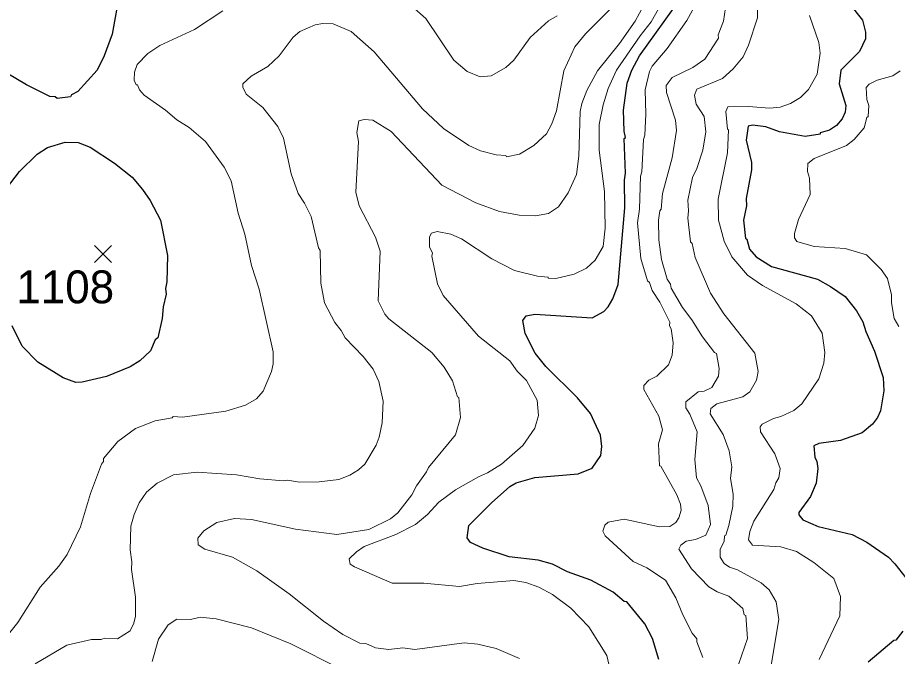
# Model space of a CAD drawing. Extents: x 265.7 to 292.1, y 7676.2 to 7704.2.
# Drawn here: x 288.593 to 290.734, y 7698.298 to 7699.854 of the extents above; entities that cross this region are included whole.
import ezdxf
from ezdxf.enums import TextEntityAlignment as Align

# ---------------------------------------------------------------- set-up
doc = ezdxf.new("R2010")
doc.units = 0
doc.header["$LTSCALE"] = 0.032
for name, color, linetype, lineweight in [('1', 7, 'Continuous', 25), ('2', 7, 'Continuous', 13), ('21', 7, 'Continuous', 25)]:
    doc.layers.add(name, color=color, linetype=linetype, lineweight=lineweight)
doc.layers.add('61', color=7, linetype='Continuous')

msp = doc.modelspace()

# ---------------------------------------------------------------- linework, layer by layer
at = {"layer": '1'}
for points in [[(288.8382, 7699.9938), (288.843, 7699.9587), (288.8398, 7699.9045), (288.823, 7699.8135), (288.8039, 7699.7608), (288.7871, 7699.7257), (288.7393, 7699.6738)], [(289.8221, 7699.1161), (289.8309, 7699.1272), (289.8516, 7699.132), (289.9913, 7699.1225), (290.0192, 7699.1384), (290.0304, 7699.1496), (290.0415, 7699.1688), (290.0543, 7699.2039), (290.0703, 7699.3906), (290.0695, 7699.4576), (290.0726, 7699.4752), (290.0687, 7699.559), (290.0719, 7699.5614), (290.0687, 7699.5773), (290.0671, 7699.6284), (290.0766, 7699.6938), (290.0878, 7699.7257), (290.1062, 7699.7608), (290.2075, 7699.9029)], [(290.6169, 7699.8869), (290.6488, 7699.8478), (290.656, 7699.8183), (290.656, 7699.8023), (290.6416, 7699.7712), (290.5961, 7699.7257), (290.5921, 7699.6922), (290.6081, 7699.6396), (290.6065, 7699.6236), (290.5993, 7699.6076), (290.5858, 7699.5909), (290.5682, 7699.5797), (290.5459, 7699.5733), (290.5459, 7699.5701), (290.5091, 7699.5645), (290.4469, 7699.5757), (290.4134, 7699.5877), (290.3815, 7699.5917), (290.3703, 7699.5893), (290.3655, 7699.555), (290.3791, 7699.5007), (290.3791, 7699.4832), (290.3655, 7699.4129), (290.3663, 7699.3954), (290.3591, 7699.3603), (290.3639, 7699.3156), (290.3671, 7699.314), (290.3743, 7699.29), (290.3902, 7699.2709), (290.4278, 7699.2477), (290.5395, 7699.2166), (290.5714, 7699.1991), (290.6065, 7699.1743), (290.6344, 7699.14), (290.6496, 7699.1129), (290.6568, 7699.089), (290.6783, 7699.0411), (290.6991, 7698.9772), (290.7006, 7698.9453), (290.6927, 7698.8959), (290.6855, 7698.8799), (290.6735, 7698.8639), (290.648, 7698.8424), (290.5953, 7698.824), (290.5427, 7698.8168), (290.5307, 7698.8113), (290.5331, 7698.7833), (290.5379, 7698.773), (290.5403, 7698.7554), (290.5363, 7698.7203), (290.5227, 7698.6876), (290.494, 7698.6485), (290.494, 7698.6429), (290.5036, 7698.6309), (290.5411, 7698.6142), (290.6241, 7698.595), (290.6592, 7698.5766), (290.7118, 7698.5399), (290.7278, 7698.524), (290.7629, 7698.4785)], [(288.7393, 7699.6738), (288.7241, 7699.6659), (288.7217, 7699.6611), (288.6898, 7699.6571), (288.6842, 7699.6611), (288.6714, 7699.6619), (288.6148, 7699.6898), (288.4962, 7699.76)], [(288.5533, 7699.4209), (288.598, 7699.4792), (288.6411, 7699.5214), (288.6658, 7699.5374), (288.7089, 7699.5502), (288.7409, 7699.5494), (288.7696, 7699.5382), (288.8286, 7699.4991), (288.8717, 7699.4648), (288.8972, 7699.4353), (288.9156, 7699.4081), (288.9411, 7699.3603), (288.9579, 7699.2741), (288.9563, 7699.2102), (288.9531, 7699.1943), (288.9547, 7699.1799), (288.9475, 7699.1496), (288.9451, 7699.1209), (288.934, 7699.0738), (288.9276, 7699.069), (288.9164, 7699.0427), (288.8909, 7699.0179), (288.8669, 7699.0036), (288.8095, 7698.9796), (288.7504, 7698.9661), (288.7345, 7698.9653), (288.7042, 7698.9764), (288.6427, 7699.0147), (288.6044, 7699.0538), (288.5797, 7699.1033)], [(290.0112, 7698.8368), (289.9873, 7698.8895), (289.9553, 7698.9278), (289.878, 7699.0044), (289.8524, 7699.0363), (289.8285, 7699.0842), (289.8221, 7699.1161)], [(290.1532, 7698.291), (290.1381, 7698.3421), (290.1189, 7698.3772), (290.0751, 7698.4314), (290.0687, 7698.4322), (290.0423, 7698.4546), (289.9881, 7698.4841), (289.9314, 7698.504), (289.8947, 7698.5232), (289.8596, 7698.5328), (289.7894, 7698.5407), (289.7255, 7698.5615), (289.6952, 7698.5759), (289.6872, 7698.587), (289.6912, 7698.6166), (289.7463, 7698.6724), (289.791, 7698.7123), (289.8061, 7698.7211), (289.8516, 7698.7338), (289.957, 7698.7426), (289.9913, 7698.7562), (290.012, 7698.7873), (290.0144, 7698.8097), (290.0112, 7698.8368)], [(290.7469, 7698.3596), (290.7302, 7698.3381), (290.7254, 7698.3373), (290.6624, 7698.2846)]]:
    msp.add_lwpolyline(points, dxfattribs=at)
at = {"layer": '2'}
for points in [[(290.2953, 7699.9811), (290.2211, 7699.847), (290.174, 7699.7784), (290.1373, 7699.7353), (290.1309, 7699.7225), (290.1197, 7699.6779), (290.1213, 7699.6188), (290.1189, 7699.5677), (290.1157, 7699.5566), (290.1118, 7699.4784), (290.1086, 7699.468), (290.1062, 7699.3874), (290.1014, 7699.3539), (290.1094, 7699.2669), (290.1261, 7699.2126), (290.1309, 7699.2087), (290.1373, 7699.1895), (290.1556, 7699.1608), (290.1804, 7699.1121), (290.1796, 7699.1033), (290.1836, 7699.0961), (290.1884, 7699.0618), (290.186, 7699.0315), (290.1772, 7699.0084), (290.1485, 7698.9804), (290.1293, 7698.9709), (290.1165, 7698.9581), (290.1165, 7698.9485), (290.1532, 7698.8831), (290.162, 7698.8496), (290.1525, 7698.8161), (290.1548, 7698.7626), (290.158, 7698.7618), (290.1971, 7698.6916), (290.2059, 7698.6692), (290.2075, 7698.6541), (290.2019, 7698.6357), (290.1947, 7698.6245), (290.1804, 7698.6142), (290.1549, 7698.6134), (290.0687, 7698.6325), (290.0304, 7698.6253), (290.0216, 7698.6181), (290.0168, 7698.603), (290.0224, 7698.5918), (290.091, 7698.5296), (290.1245, 7698.5136), (290.1692, 7698.4841), (290.1947, 7698.441), (290.2115, 7698.3995), (290.2346, 7698.3548), (290.2458, 7698.3413), (290.2458, 7698.3341), (290.2602, 7698.2958)], [(290.2801, 7698.9022), (290.2945, 7698.9134), (290.3575, 7698.9302), (290.3751, 7698.9421), (290.391, 7698.9709), (290.395, 7698.9916), (290.387, 7699.0363), (290.3112, 7699.1328), (290.2793, 7699.1831), (290.2418, 7699.2693), (290.2346, 7699.3036), (290.2307, 7699.3076), (290.2235, 7699.3651), (290.2259, 7699.3834), (290.2235, 7699.4089), (290.2354, 7699.464), (290.2458, 7699.4863), (290.2602, 7699.531), (290.2674, 7699.5757), (290.2634, 7699.6132), (290.2442, 7699.6427), (290.2402, 7699.6651), (290.2458, 7699.6794), (290.3081, 7699.7058), (290.3344, 7699.7289), (290.3583, 7699.7584), (290.3719, 7699.7864), (290.3934, 7699.8534), (290.3918, 7699.9468)], [(290.265, 7699.7529), (290.2985, 7699.8039), (290.2977, 7699.8119), (290.3104, 7699.8454), (290.3152, 7699.8773), (290.3152, 7699.9125), (290.324, 7699.9603)], [(290.1852, 7699.9332), (290.1349, 7699.8438), (290.1078, 7699.8095), (290.0503, 7699.7257), (290.0304, 7699.681), (290.0176, 7699.6411), (290.008, 7699.5933), (290.008, 7699.531), (290.0208, 7699.4305), (290.0224, 7699.3411), (290.0176, 7699.2964), (289.9984, 7699.2629), (289.9777, 7699.2437), (289.9474, 7699.2286), (289.9027, 7699.2182), (289.8843, 7699.219), (289.8843, 7699.2214), (289.858, 7699.2238), (289.8022, 7699.2382), (289.7471, 7699.2661), (289.6729, 7699.3148), (289.6473, 7699.3267), (289.6138, 7699.3331), (289.6003, 7699.3291), (289.5955, 7699.3196), (289.5955, 7699.2948), (289.6027, 7699.2813), (289.6011, 7699.2725), (289.6146, 7699.2055), (289.6282, 7699.1767), (289.7144, 7699.0778), (289.791, 7699.0179), (289.8085, 7698.9932), (289.8317, 7698.9701), (289.8572, 7698.9222), (289.8604, 7698.8847), (289.8516, 7698.8544), (289.8221, 7698.8121), (289.7702, 7698.7666), (289.7367, 7698.745), (289.7144, 7698.7355), (289.6585, 7698.7035), (289.6178, 7698.674), (289.5907, 7698.6437), (289.5612, 7698.6197), (289.5133, 7698.595), (289.4367, 7698.5655), (289.4175, 7698.5527), (289.4, 7698.536), (289.4024, 7698.5232), (289.4127, 7698.516), (289.5045, 7698.4769), (289.5819, 7698.4769), (289.6681, 7698.4681), (289.7112, 7698.4761), (289.8006, 7698.4833), (289.8301, 7698.4785), (289.8612, 7698.4665), (289.8947, 7698.449), (289.9394, 7698.4155), (289.9833, 7698.37), (290.0272, 7698.3006), (290.0399, 7698.2447)], [(289.0321, 7698.5703), (289.0313, 7698.5862), (289.0465, 7698.6038), (289.0776, 7698.6245), (289.1207, 7698.6341), (289.1622, 7698.6317), (289.2691, 7698.6078), (289.3697, 7698.595), (289.4479, 7698.607), (289.5005, 7698.6333), (289.5181, 7698.6477), (289.5524, 7698.6916), (289.5636, 7698.7139), (289.5883, 7698.7474), (289.5931, 7698.7586), (289.6585, 7698.8376), (289.6705, 7698.8799), (289.6665, 7698.9286), (289.6633, 7698.9302), (289.6513, 7698.9693), (289.6314, 7699.0028), (289.6011, 7699.0379), (289.4965, 7699.1201), (289.487, 7699.1312), (289.4702, 7699.164), (289.475, 7699.2852), (289.4638, 7699.3188), (289.4239, 7699.3954), (289.4159, 7699.4289), (289.4223, 7699.5518), (289.4183, 7699.5741), (289.4231, 7699.602), (289.4367, 7699.606), (289.4574, 7699.6036), (289.5021, 7699.5765), (289.625, 7699.4456), (289.708, 7699.4025), (289.7654, 7699.3818), (289.8133, 7699.373), (289.8532, 7699.3714), (289.8851, 7699.377), (289.9091, 7699.393), (289.933, 7699.4273), (289.953, 7699.472), (289.9585, 7699.5167), (289.9617, 7699.6252), (289.9657, 7699.6443), (289.9785, 7699.6763), (290.004, 7699.7241), (290.0575, 7699.7904), (290.0958, 7699.8454), (290.1165, 7699.8837)], [(290.0511, 7699.8909), (289.9753, 7699.8143), (289.949, 7699.7824), (289.9218, 7699.7241), (289.9043, 7699.6268), (289.8931, 7699.5949), (289.8803, 7699.5709), (289.8492, 7699.5422), (289.8141, 7699.5214), (289.783, 7699.5151), (289.7814, 7699.5183), (289.7575, 7699.5198), (289.7192, 7699.5294), (289.6912, 7699.5422), (289.629, 7699.5837), (289.5787, 7699.6316)], [(289.0928, 7699.8702), (289.0233, 7699.8247), (288.9388, 7699.7856), (288.91, 7699.7664), (288.8837, 7699.7393), (288.8773, 7699.7209), (288.8765, 7699.7018), (288.8813, 7699.6898), (288.8845, 7699.6898), (288.8901, 7699.6778), (288.9012, 7699.6651), (288.9531, 7699.6284), (288.9802, 7699.6052), (289.0106, 7699.5861)], [(289.9059, 7699.8582), (289.8851, 7699.8462), (289.8405, 7699.8055), (289.8006, 7699.7497), (289.7814, 7699.7321), (289.7455, 7699.7122), (289.7184, 7699.7098), (289.6872, 7699.7225), (289.6545, 7699.7497), (289.5867, 7699.8518), (289.5532, 7699.8805)], [(289.5787, 7699.6316), (289.4606, 7699.7704), (289.4048, 7699.8199), (289.3609, 7699.8382), (289.3361, 7699.839), (289.317, 7699.8358), (289.2795, 7699.8199)], [(290.4054, 7699.2015), (290.3687, 7699.2262), (290.3312, 7699.2709), (290.312, 7699.3092), (290.2985, 7699.3603), (290.2977, 7699.4113), (290.32, 7699.5246), (290.3232, 7699.5805), (290.32, 7699.5821), (290.316, 7699.6252), (290.3216, 7699.6364), (290.3719, 7699.6372), (290.423, 7699.6332), (290.4485, 7699.6356), (290.474, 7699.6443), (290.498, 7699.6595), (290.5171, 7699.6786), (290.5387, 7699.7162), (290.5458, 7699.7672), (290.5427, 7699.7928), (290.5203, 7699.859)], [(289.2795, 7699.8199), (289.2635, 7699.8063), (289.2292, 7699.7608), (289.2021, 7699.7345), (289.1614, 7699.7114), (289.1414, 7699.6922), (289.1414, 7699.6842), (289.1494, 7699.6675), (289.1901, 7699.6347), (289.226, 7699.5885), (289.2404, 7699.5598), (289.2587, 7699.4736), (289.2755, 7699.4257), (289.2915, 7699.4018), (289.3074, 7699.3698), (289.325, 7699.2932), (289.329, 7699.2869), (289.3306, 7699.2071), (289.3401, 7699.1592), (289.3649, 7699.1113), (289.3808, 7699.0921), (289.3904, 7699.0738), (289.4343, 7699.0283), (289.4582, 7698.998), (289.4718, 7698.9677), (289.4822, 7698.9198), (289.4798, 7698.8671), (289.4726, 7698.832), (289.4654, 7698.8129), (289.4383, 7698.7666), (289.4223, 7698.7522), (289.4016, 7698.7394), (289.3744, 7698.7291), (289.3266, 7698.7235), (289.2787, 7698.7227), (289.25, 7698.7275), (289.2404, 7698.7259), (289.1829, 7698.7307), (289.1255, 7698.7402), (289.0297, 7698.7466), (288.9723, 7698.7402), (288.9324, 7698.7203), (288.9068, 7698.6979), (288.8893, 7698.6724), (288.8765, 7698.6437), (288.8685, 7698.615), (288.8669, 7698.5575), (288.8709, 7698.5288), (288.8701, 7698.5096), (288.8797, 7698.4426), (288.8797, 7698.3963), (288.8757, 7698.3788), (288.8669, 7698.3604), (288.8366, 7698.3413), (288.8047, 7698.3429), (288.7967, 7698.3397), (288.7728, 7698.3397), (288.7129, 7698.3253), (288.6355, 7698.2798)], [(290.3328, 7698.2367), (290.3687, 7698.3421), (290.3647, 7698.3979), (290.3607, 7698.3995), (290.3575, 7698.4147), (290.324, 7698.445), (290.2953, 7698.4554), (290.2753, 7698.4673), (290.233, 7698.5112), (290.2019, 7698.5591), (290.2067, 7698.5687), (290.2195, 7698.5791), (290.2426, 7698.583), (290.2674, 7698.5934), (290.2793, 7698.6198), (290.2737, 7698.666), (290.2554, 7698.7139), (290.245, 7698.7331), (290.241, 7698.7778), (290.2466, 7698.8448), (290.2291, 7698.8879), (290.2187, 7698.9038), (290.2187, 7698.9182), (290.249, 7698.9421), (290.2634, 7698.9437), (290.2825, 7698.9533), (290.2985, 7698.9804), (290.3001, 7698.9996), (290.2937, 7699.0355), (290.2889, 7699.0379), (290.2594, 7699.0762), (290.2338, 7699.1177), (290.2107, 7699.148), (290.1836, 7699.1951), (290.182, 7699.2047), (290.174, 7699.2166), (290.1596, 7699.2645), (290.1532, 7699.3124), (290.1525, 7699.3603), (290.1556, 7699.3834), (290.1588, 7699.3874), (290.162, 7699.4257), (290.186, 7699.5119), (290.1963, 7699.5789), (290.1939, 7699.6044), (290.1716, 7699.6715), (290.1708, 7699.6882), (290.186, 7699.7082), (290.2362, 7699.7321), (290.265, 7699.7529)], [(290.7406, 7699.7241), (290.723, 7699.7122), (290.6847, 7699.7018), (290.6655, 7699.6914), (290.6576, 7699.6834), (290.6592, 7699.6547), (290.6639, 7699.6396), (290.6623, 7699.6132), (290.6592, 7699.6108), (290.6528, 7699.5853), (290.6288, 7699.5566), (290.6097, 7699.5422), (290.5315, 7699.5103), (290.5155, 7699.4983), (290.5147, 7699.4792), (290.5203, 7699.4624), (290.5219, 7699.4233), (290.4932, 7699.3619), (290.4836, 7699.3283), (290.4836, 7699.3172), (290.4892, 7699.3084), (290.5315, 7699.2964), (290.6065, 7699.2916), (290.6584, 7699.2757), (290.6943, 7699.2406), (290.7094, 7699.2182), (290.7198, 7699.1783), (290.7198, 7699.1592), (290.7262, 7699.1209), (290.7374, 7699.1017)], [(289.0106, 7699.5861), (289.0505, 7699.5518), (289.0959, 7699.4895), (289.1127, 7699.456), (289.1295, 7699.3778), (289.1462, 7699.3267), (289.1622, 7699.2501)], [(289.1622, 7699.2501), (289.1805, 7699.1927), (289.2149, 7699.0395), (289.2148, 7699.0108), (289.2109, 7698.9916), (289.1909, 7698.9437), (289.1742, 7698.9254), (289.1478, 7698.9102), (289.0999, 7698.895), (288.9946, 7698.8807), (288.9715, 7698.8823), (288.9691, 7698.8791), (288.9276, 7698.8719), (288.8797, 7698.8528), (288.8374, 7698.8216), (288.8023, 7698.7801), (288.8023, 7698.773), (288.7975, 7698.7666), (288.7704, 7698.6948), (288.7464, 7698.6134), (288.7137, 7698.5463), (288.6938, 7698.5176), (288.6483, 7698.4665), (288.594, 7698.3804), (288.5709, 7698.3524)], [(290.5427, 7698.9741), (290.5546, 7699.0124), (290.557, 7699.0379), (290.5506, 7699.085), (290.5251, 7699.1273), (290.4876, 7699.1568), (290.4054, 7699.2015)], [(290.5435, 7698.291), (290.5937, 7698.3971), (290.5953, 7698.4442), (290.5794, 7698.4881), (290.5307, 7698.5272), (290.4884, 7698.5535), (290.4501, 7698.5647), (290.3815, 7698.5687), (290.3719, 7698.5822), (290.3751, 7698.6022), (290.3847, 7698.6277), (290.4333, 7698.7043), (290.4381, 7698.7211), (290.4453, 7698.7331), (290.4485, 7698.7554), (290.4357, 7698.7913), (290.4006, 7698.8448), (290.3998, 7698.8575), (290.4046, 7698.8639), (290.4325, 7698.8775), (290.4501, 7698.8823), (290.482, 7698.8974), (290.5012, 7698.9134), (290.5427, 7698.9741)], [(290.3344, 7698.6932), (290.328, 7698.7315), (290.3312, 7698.7602), (290.3248, 7698.7985), (290.3096, 7698.8384), (290.2785, 7698.8887), (290.2801, 7698.9022)], [(290.4214, 7698.2479), (290.4453, 7698.3883), (290.4389, 7698.4314), (290.4214, 7698.4602), (290.4022, 7698.4777), (290.3448, 7698.5088), (290.3256, 7698.5152), (290.312, 7698.5248), (290.3025, 7698.54), (290.3025, 7698.5591), (290.312, 7698.5783), (290.3128, 7698.5918), (290.316, 7698.5934), (290.324, 7698.6166), (290.3336, 7698.6644), (290.3344, 7698.6932)], [(289.3848, 7698.3516), (289.3377, 7698.3844), (289.254, 7698.4506), (289.175, 7698.5064), (289.1159, 7698.54), (289.0489, 7698.5591), (289.0321, 7698.5703)], [(288.9204, 7698.2862), (288.9356, 7698.3405), (288.9595, 7698.3748), (288.9803, 7698.3891), (289.0138, 7698.3883), (289.0377, 7698.3939), (289.076, 7698.3899), (289.1622, 7698.3676), (289.2579, 7698.3285), (289.3808, 7698.267)], [(289.8141, 7698.2934), (289.7575, 7698.3173), (289.7128, 7698.3277), (289.6793, 7698.3309), (289.5596, 7698.3149), (289.5308, 7698.3189), (289.4965, 7698.3149), (289.4638, 7698.3189), (289.4407, 7698.3293), (289.4255, 7698.3301), (289.3848, 7698.3516)]]:
    msp.add_lwpolyline(points, dxfattribs=at)
at = {"layer": '21'}
for p, q in [((288.7802, 7699.299), (288.8214, 7699.2578)), ((288.8214, 7699.299), (288.7802, 7699.2578))]:
    msp.add_line(p, q, dxfattribs=at)

# ---------------------------------------------------------------- texts
at = {"layer": '61'}
msp.add_text('1108', height=0.08, dxfattribs=at).set_placement((288.709, 7699.1581), align=Align.CENTER)

doc.saveas('drawing.dxf')
